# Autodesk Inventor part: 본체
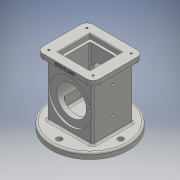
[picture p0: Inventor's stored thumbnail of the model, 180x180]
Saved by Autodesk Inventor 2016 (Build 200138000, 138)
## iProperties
Created: 2018-10
Part Number: 본체
Material: 일반
Document SubType Name: Modeling
Designer: USER
Density: 1 g/cm^3
Appearance: 기본값
Author: USER
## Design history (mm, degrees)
sketch "스케치3"
  geometry: C1 r 62.5 at (0, 0); 1 further point
  constraints: 1 centre point, 1 coincident
  dimensions: "d4" = 125 diameter of C1
extrude "돌출2" new body sketch "스케치3" distance "d5" = 10; taper "d6" = 0 deg
sketch "스케치4"
  geometry: L1 (-37, -33)-(37, -33); L2 (37, -33)-(37, 33); L3 (37, 33)-(-37, 33); L4 (-37, 33)-(-37, -33); L5 (-37, -33)-(37, 33); L6 (37, -33)-(-37, 33); 1 further point
  constraints: 12 end point, 2 midpoint, 2 parallel, 1 horizontal, 1 perpendicular
  dimensions: "d7" = 74 distance of L2.end L3.end; "d8" = 66 distance of L1.end L2.end
extrude "돌출3" join sketch "스케치4" distance "d9" = 88; taper "d10" = 0 deg
sketch "스케치5"
  geometry: L1 (-46, -41)-(46, -41); L2 (46, -41)-(46, 41); L3 (46, 41)-(-46, 41); L4 (-46, 41)-(-46, -41); L5 (-46, -41)-(46, 41); L6 (46, -41)-(-46, 41); 1 further point
  constraints: 12 end point, 2 midpoint, 2 parallel, 1 horizontal, 1 perpendicular
  dimensions: "d11" = 92 distance of L2.end L3.end; "d12" = 82 distance of L1.end L2.end
extrude "돌출4" join sketch "스케치5" distance "d13" = 10; taper "d14" = 0 deg
sketch "스케치6"
  geometry: L1 (-26, -26)-(26, -26); L2 (26, -26)-(26, 26); L3 (26, 26)-(-26, 26); L4 (-26, 26)-(-26, -26); L5 (-26, -26)-(26, 26); L6 (26, -26)-(-26, 26); 1 further point
  constraints: 12 end point, 2 midpoint, 2 parallel, 1 horizontal, 1 perpendicular
  dimensions: "d15" = 52 distance of L2.end L3.end; "d16" = 52 distance of L1.end L2.end
extrude "돌출5" cut sketch "스케치6" distance "d17" = 8; taper "d18" = 0 deg
sketch "스케치7"
  geometry: L1 (-22, -22)-(22, -22); L2 (22, -22)-(22, 22); L3 (22, 22)-(-22, 22); L4 (-22, 22)-(-22, -22); L5 (-22, -22)-(22, 22); L6 (22, -22)-(-22, 22); 1 further point
  constraints: 12 end point, 2 midpoint, 2 parallel, 1 horizontal, 1 perpendicular
  dimensions: "d19" = 44 distance of L2.end L3.end; "d20" = 44 distance of L1.end L2.end
extrude "돌출6" cut sketch "스케치7" distance "d21" = 74; taper "d22" = 0 deg
sketch "스케치8"
  geometry: C1 r 28 at (0, 0); 1 further point
  constraints: 1 centre point, 1 coincident
  dimensions: "d23" = 56 diameter of C1
extrude "돌출7" cut sketch "스케치8" distance "d24" = 18; taper "d25" = -10 deg
sketch "스케치9"
  geometry: L1 (74, 0)-(0, 0) reference; L2 (74, 0)-(74, 88) reference; L3 (0, 88)-(74, 88) reference; L4 (0, 0)-(0, 88) reference; L5 (99.5, 0)-(-25.5, 0) reference; L6 (-25.5, -10)-(99.5, -10) reference; 2 further points
  dimensions: "d26" = 54 distance from line of L6 point (37, 44); "d27" = 37 distance from line of L2 point (37, 44)
hole "구멍1" sketch "스케치9" at (37, 44) diameter "d28" = 48; stored, may be unused: countersink angle "d32" = 90 deg, drill point angle "d34" = 0 deg; dims "d29" = 6, "d30" = 70, "d31" = 3, "d33" = 11
sketch "스케치10"
  geometry: C1 r 24 at (37, -44) reference; C2 r 35 at (37, -44); 1 further point
  constraints: 1 centre point, 1 coincident
  dimensions: "d35" = 70 diameter of C2
extrude "돌출8" cut sketch "스케치10" distance "d36" = 3; taper "d37" = 0 deg
fillet "모깎기1" dims "d38" = 3
sketch "스케치11"
  geometry: 2 further points
  constraints: 1 vertical alignment
  dimensions: "d39" = 50 distance of point (0, 0) point (0, 50)
hole "구멍2" sketch "스케치11" at (0, 50) diameter "d40" = 9; stored, may be unused: countersink angle "d44" = 90 deg, drill point angle "d46" = 118 deg; dims "d41" = 6, "d42" = 70, "d43" = 3, "d45" = 11
sketch "스케치12"
  geometry: L1 (10, -29.5)-(10, 95.5) reference; L2 (0, 66)-(-88, 66) reference; 3 further points
  constraints: 1 horizontal alignment
  dimensions: "d50" = 37 distance from line of L1 point (-27, 33); "d51" = 43 distance of point (-27, 33) point (-70, 33); "d52" = 33 distance from line of L2 point (-27, 33)
hole "구멍3" sketch "스케치12" at (-27, 33), (-70, 33) diameter "d53" = 4.134; stored, may be unused: countersink angle "d57" = 90 deg, drill point angle "d59" = 118 deg; dims "d54" = 30, "d55" = 70, "d56" = 3, "d58" = 30
sketch "스케치13"
  geometry: L1 (46, 41)-(-46, 41) reference; L2 (46, -41)-(46, 41) reference; 2 further points
  dimensions: "d60" = 10 distance from line of L1 point (36, 31); "d61" = 10 distance from line of point (36, 31) L2
hole "구멍4" sketch "스케치13" at (36, 31) diameter "d62" = 3.242; stored, may be unused: countersink angle "d66" = 90 deg, drill point angle "d68" = 118 deg; dims "d63" = 4, "d64" = 70, "d65" = 3, "d67" = 6
sketch "스케치14"
  geometry: C1 r 24 at (0, 0) reference; 2 further points
  constraints: 1 vertical alignment
  dimensions: "d75" = 29 distance of C1.centre point (0, 29)
hole "구멍5" sketch "스케치14" at (0, 29) diameter "d76" = 3.242; stored, may be unused: countersink angle "d80" = 90 deg, drill point angle "d82" = 118 deg; dims "d77" = 4, "d78" = 70, "d79" = 3, "d81" = 6
node "작업 평면1"
fillet "모깎기2" dims "d87" = 3
chamfer "모따기1" distance "d88" = 1; stored, may be unused: second distance "d89" = 2, angle "d90" = 45 deg
fillet "모깎기4" dims "d92" = 3
fillet "모깎기5" dims "d93" = 3
fillet "모깎기6" dims "d94" = 3
fillet "모깎기7" dims "d95" = 3
fillet "모깎기8" dims "d96" = 10
fillet "모깎기9" dims "d97" = 3
fillet "모깎기10" dims "d98" = 3
sketch "스케치15"
  geometry: L1 (0, 0)-(72, 0) reference; L2 (-10, 0)-(-10, -7) reference; 2 further points
  constraints: 1 other
  dimensions: "d99" = 4 distance from line of L1 point (36, -4); "d100" = 46 distance from line of point (36, -4) L2
feature "엠보싱1" sketch "스케치15" dims "d4" = 125, "d101" = 0.5, "d102" = 0
fillet "모깎기11" dims "d103" = 3
node "솔리드2"
pattern_circular "원형 패턴1" dims angle "d48" = 360 deg
pattern_linear "직사각형 패턴1" dims "d71" = 72, "d74" = 62
pattern_circular "원형 패턴2" dims angle "d84" = 360 deg
mirror "대칭1"
node "투영된 루프1"
other parameters: "d86" = 0
